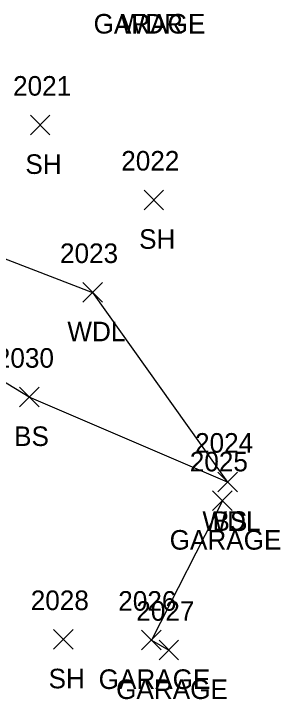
# Model space of a CAD drawing. Extents: x 1761340 to 1763889, y 696770 to 706023.
# Drawn here: x 1761860 to 1761887.3, y 700733 to 700803.1 of the extents above; entities that cross this region are included whole.
import ezdxf

# ---------------------------------------------------------------- set-up
doc = ezdxf.new("R2010")
doc.units = 0
for name, color, linetype in [('L_A', 7, 'Continuous'), ('L_I', 7, 'Continuous'), ('L_TIC', 7, 'Continuous'), ('LAWA', 7, 'Continuous'), ('LBC', 7, 'Continuous'), ('LELB', 7, 'Continuous')]:
    doc.layers.add(name, color=color, linetype=linetype)

msp = doc.modelspace()

# ---------------------------------------------------------------- linework, layer by layer
at = {"layer": 'L_TIC'}
for points in [[(1761861.699, 700790.753), (1761863.699, 700792.753)], [(1761863.699, 700790.753), (1761861.699, 700792.753)], [(1761873.343, 700783.097), (1761875.343, 700785.097)], [(1761875.343, 700783.097), (1761873.343, 700785.097)], [(1761867.069, 700773.644), (1761869.069, 700775.644)], [(1761869.069, 700773.644), (1761867.069, 700775.644)], [(1761860.589, 700762.942), (1761862.589, 700764.942)], [(1761862.589, 700762.942), (1761860.589, 700764.942)], [(1761880.898, 700754.259), (1761882.898, 700756.259)], [(1761882.898, 700754.259), (1761880.898, 700756.259)], [(1761880.898, 700754.259), (1761882.898, 700756.259)], [(1761882.898, 700754.259), (1761880.898, 700756.259)], [(1761880.362, 700752.347), (1761882.362, 700754.347)], [(1761882.362, 700752.347), (1761880.362, 700754.347)], [(1761864.075, 700738.169), (1761866.075, 700740.169)], [(1761866.075, 700738.169), (1761864.075, 700740.169)], [(1761873.091, 700738.105), (1761875.091, 700740.105)], [(1761875.091, 700738.105), (1761873.091, 700740.105)], [(1761874.88, 700737.078), (1761876.88, 700739.078)], [(1761876.88, 700737.078), (1761874.88, 700739.078)]]:
    msp.add_lwpolyline(points, dxfattribs=at)
at = {"layer": 'LAWA'}
msp.add_lwpolyline([(1761808.64, 700793.788), (1761818.4, 700785.774), (1761840.969, 700785.066), (1761868.069, 700774.644), (1761881.898, 700755.259)], dxfattribs=at)
at = {"layer": 'LBC'}
msp.add_lwpolyline([(1761881.362, 700753.347), (1761874.091, 700739.105), (1761875.88, 700738.078)], dxfattribs=at)
at = {"layer": 'LELB'}
msp.add_lwpolyline([(1761881.898, 700755.259), (1761861.589, 700763.942), (1761840.773, 700776.572), (1761820.648, 700780.11), (1761819.332, 700774.91)], dxfattribs=at)

# ---------------------------------------------------------------- texts
at = {"layer": 'L_A'}
for s, p in [('GARAGE', (1761868.173, 700801.1)), ('WDR', (1761870.937, 700801.1)), ('SH', (1761861.187, 700786.753)), ('SH', (1761872.831, 700779.097)), ('WDL', (1761865.487, 700769.644)), ('BS', (1761860.03, 700758.942)), ('BS', (1761880.339, 700750.259)), ('WDL', (1761879.316, 700750.259)), ('GARAGE', (1761875.96, 700748.347)), ('SH', (1761863.563, 700734.169)), ('GARAGE', (1761868.689, 700734.105)), ('GARAGE', (1761870.479, 700733.078))]:
    msp.add_text(s, height=2, dxfattribs=at).set_placement(p)
at = {"layer": 'L_I'}
for s, p in [('2021', (1761859.927, 700794.753)), ('2022', (1761871.004, 700787.097)), ('2023', (1761864.731, 700777.644)), ('2030', (1761858.164, 700766.942)), ('2024', (1761878.56, 700758.259)), ('2024', (1761878.56, 700758.259)), ('2025', (1761878.023, 700756.347)), ('2028', (1761861.736, 700742.169)), ('2026', (1761870.697, 700742.105)), ('2027', (1761872.542, 700741.078))]:
    msp.add_text(s, height=2, dxfattribs=at).set_placement(p)

doc.saveas('drawing.dxf')
